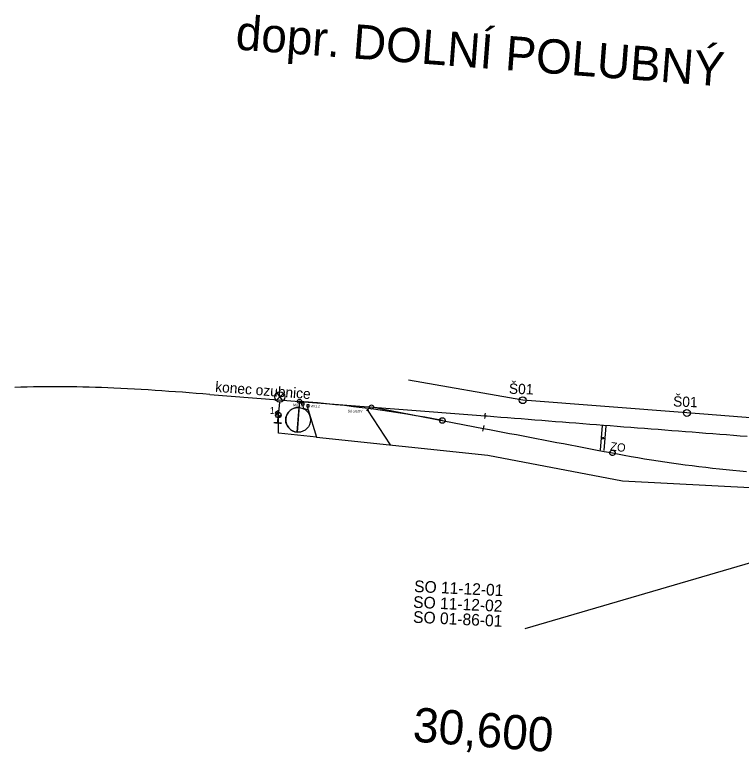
# Model space of a CAD drawing. Extents: x -669628 to -669207, y -977198 to -977075.
# Drawn here: x -669628.1 to -669522.2, y -977182.8 to -977075.4 of the extents above; entities that cross this region are included whole.
import ezdxf

# ---------------------------------------------------------------- set-up
doc = ezdxf.new("R2010")
doc.units = 0
for name, color, linetype in [('_PS_SO_číslo', 7, 'Continuous'), ('KOL_námezníky', 7, 'Continuous'), ('Navazující stavba', 7, 'Continuous'), ('SO 01-86-01', 7, 'Continuous'), ('SO 11-10-01', 7, 'Continuous'), ('SO 11-11-01', 7, 'Continuous')]:
    doc.layers.add(name, color=color, linetype=linetype)

# ---------------------------------------------------------------- blocks, each defined once
blk = doc.blocks.new('POINT_DISPLAY')
blk.add_line((0, 0), (0, 0))
blk = doc.blocks.new('Z3.50')
at = {"layer": 'KOL_námezníky'}
for p, q in [((-28, 181), (-26, -175)), ((33, -175), (32, 181))]:
    blk.add_line(p, q, dxfattribs=at)

msp = doc.modelspace()

# ---------------------------------------------------------------- linework, layer by layer
at = {"layer": '_PS_SO_číslo'}
msp.add_line((-669553.76, -977164.78), (-669513.23, -977152.92), dxfattribs=at)
at = {"layer": 'Navazující stavba'}
msp.add_line((-669599.7, -977130.69), (-669586.62, -977131.71), dxfattribs=at)
msp.add_lwpolyline([(-669599.7, -977130.69), (-669600.7, -977130.61), (-669601.69, -977130.53), (-669602.69, -977130.46), (-669603.69, -977130.38), (-669604.69, -977130.31), (-669605.68, -977130.24), (-669606.68, -977130.17), (-669607.68, -977130.1), (-669608.68, -977130.03), (-669609.68, -977129.97), (-669610.67, -977129.91), (-669611.67, -977129.86), (-669612.67, -977129.81), (-669613.67, -977129.76)], dxfattribs=at)
msp.add_arc((-669622.21, -977329.58), 200, 87.5523, 91.6942, dxfattribs=at)
at = {"layer": 'SO 01-86-01'}
for p, q in [((-669590.04, -977131.57), (-669588.95, -977130.54)), ((-669589.95, -977130.46), (-669589.04, -977131.65)), ((-669589.55, -977131.8), (-669589.67, -977133.3)), ((-669585.95, -977131.94), (-669586.33, -977131.94)), ((-669586.33, -977131.94), (-669586.33, -977132.22)), ((-669585.95, -977132.22), (-669585.95, -977131.94)), ((-669586.33, -977132.22), (-669585.95, -977132.22)), ((-669586.14, -977132.22), (-669586.1, -977132.67)), ((-669586.1, -977132.67), (-669585.38, -977132.95)), ((-669585.21, -977132.21), (-669585.58, -977132.21)), ((-669585.58, -977132.21), (-669585.58, -977132.49)), ((-669585.58, -977132.49), (-669585.21, -977132.49)), ((-669585.38, -977132.95), (-669585.39, -977132.49)), ((-669585.38, -977132.95), (-669584.14, -977136.93)), ((-669585.21, -977132.49), (-669585.21, -977132.21)), ((-669576.7, -977132.96), (-669573.41, -977138.03)), ((-669590.09, -977133.75), (-669589.59, -977133.31)), ((-669589.85, -977134.06), (-669589.31, -977133.6)), ((-669589.67, -977136.35), (-669589.71, -977133.74)), ((-669584.14, -977136.93), (-669589.67, -977136.35)), ((-669584.14, -977136.93), (-669559.19, -977139.53)), ((-669559.19, -977139.53), (-669539.54, -977143.26)), ((-669539.54, -977143.26), (-669520.01, -977144.3))]:
    msp.add_line(p, q, dxfattribs=at)
for centre, radius in [((-669589.49, -977131.06), 0.749), ((-669576.7, -977132.96), 0.0916), ((-669589.7, -977133.7), 0.4)]:
    msp.add_circle(centre, radius, dxfattribs=at)
at = {"layer": 'SO 11-10-01'}
for p, q in [((-669586.62, -977131.71), (-669586.97, -977136.19)), ((-669586.62, -977131.71), (-669559.57, -977133.81)), ((-669576.13, -977132.52), (-669559.81, -977135.63)), ((-669559.57, -977133.81), (-669559.29, -977133.83)), ((-669559.29, -977133.83), (-669558.29, -977133.91)), ((-669558.29, -977133.91), (-669557.3, -977133.99)), ((-669557.3, -977133.99), (-669556.3, -977134.07)), ((-669556.3, -977134.07), (-669555.3, -977134.14)), ((-669555.3, -977134.14), (-669554.3, -977134.22)), ((-669554.3, -977134.22), (-669553.31, -977134.3)), ((-669553.31, -977134.3), (-669552.31, -977134.38)), ((-669552.31, -977134.38), (-669551.31, -977134.46)), ((-669551.31, -977134.46), (-669550.32, -977134.53)), ((-669550.32, -977134.53), (-669549.32, -977134.61)), ((-669549.32, -977134.61), (-669548.32, -977134.69)), ((-669548.32, -977134.69), (-669547.33, -977134.77)), ((-669547.33, -977134.77), (-669546.33, -977134.84)), ((-669546.33, -977134.84), (-669545.33, -977134.92)), ((-669545.33, -977134.92), (-669544.33, -977135)), ((-669544.33, -977135), (-669543.34, -977135.08)), ((-669543.34, -977135.08), (-669542.34, -977135.15)), ((-669542.34, -977135.15), (-669541.34, -977135.23)), ((-669541.34, -977135.23), (-669540.35, -977135.31)), ((-669559.81, -977135.63), (-669558.94, -977135.8)), ((-669558.94, -977135.8), (-669557.96, -977135.99)), ((-669557.96, -977135.99), (-669556.98, -977136.17)), ((-669556.98, -977136.17), (-669556, -977136.36)), ((-669540.35, -977135.31), (-669539.35, -977135.39)), ((-669539.35, -977135.39), (-669538.35, -977135.46)), ((-669538.35, -977135.46), (-669537.36, -977135.54)), ((-669537.36, -977135.54), (-669536.36, -977135.62)), ((-669536.36, -977135.62), (-669535.36, -977135.7)), ((-669535.36, -977135.7), (-669534.36, -977135.77)), ((-669534.36, -977135.77), (-669533.37, -977135.85)), ((-669533.37, -977135.85), (-669532.37, -977135.93)), ((-669532.37, -977135.93), (-669531.37, -977136.01)), ((-669531.37, -977136.01), (-669530.38, -977136.08)), ((-669530.38, -977136.08), (-669529.38, -977136.16)), ((-669529.38, -977136.16), (-669528.38, -977136.24)), ((-669528.38, -977136.24), (-669527.39, -977136.32)), ((-669556, -977136.36), (-669555.02, -977136.55)), ((-669555.02, -977136.55), (-669554.03, -977136.74)), ((-669554.03, -977136.74), (-669553.05, -977136.92)), ((-669553.05, -977136.92), (-669552.07, -977137.11)), ((-669552.07, -977137.11), (-669551.09, -977137.3)), ((-669551.09, -977137.3), (-669550.1, -977137.48)), ((-669542.57, -977136.98), (-669542.19, -977137.11)), ((-669542.44, -977137.23), (-669542.32, -977136.85)), ((-669527.39, -977136.32), (-669526.39, -977136.4)), ((-669526.39, -977136.4), (-669525.39, -977136.47)), ((-669525.39, -977136.47), (-669524.39, -977136.55)), ((-669524.39, -977136.55), (-669523.4, -977136.63)), ((-669523.4, -977136.63), (-669522.4, -977136.71)), ((-669522.4, -977136.71), (-669521.4, -977136.78)), ((-669550.1, -977137.48), (-669549.12, -977137.67)), ((-669549.12, -977137.67), (-669548.14, -977137.86)), ((-669548.14, -977137.86), (-669547.16, -977138.05)), ((-669547.16, -977138.05), (-669546.17, -977138.23)), ((-669546.17, -977138.23), (-669545.19, -977138.42)), ((-669545.19, -977138.42), (-669544.21, -977138.61)), ((-669544.21, -977138.61), (-669543.23, -977138.8)), ((-669543.23, -977138.8), (-669542.24, -977138.98)), ((-669542.24, -977138.98), (-669541.26, -977139.17)), ((-669541.26, -977139.17), (-669541.02, -977139.22)), ((-669541.02, -977139.22), (-669540.28, -977139.36)), ((-669540.28, -977139.36), (-669539.3, -977139.54)), ((-669539.3, -977139.54), (-669538.31, -977139.71)), ((-669538.31, -977139.71), (-669537.33, -977139.88)), ((-669537.33, -977139.88), (-669536.34, -977140.05)), ((-669536.34, -977140.05), (-669535.35, -977140.21)), ((-669535.35, -977140.21), (-669534.37, -977140.36)), ((-669534.37, -977140.36), (-669533.38, -977140.51)), ((-669533.38, -977140.51), (-669532.39, -977140.66)), ((-669532.39, -977140.66), (-669531.4, -977140.8)), ((-669531.4, -977140.8), (-669530.41, -977140.93)), ((-669530.41, -977140.93), (-669529.41, -977141.06)), ((-669529.41, -977141.06), (-669528.42, -977141.18)), ((-669528.42, -977141.18), (-669527.43, -977141.3)), ((-669527.43, -977141.3), (-669526.44, -977141.41)), ((-669526.44, -977141.41), (-669525.44, -977141.52)), ((-669525.44, -977141.52), (-669524.45, -977141.62)), ((-669524.45, -977141.62), (-669523.45, -977141.72)), ((-669523.45, -977141.72), (-669522.46, -977141.81)), ((-669522.46, -977141.81), (-669521.46, -977141.9))]:
    msp.add_line(p, q, dxfattribs=at)
for points in [[(-669586.97, -977136.19), (-669586.69, -977132.6), (-669586.69, -977132.6)], [(-669541.09, -977139.61), (-669541.22, -977139.56), (-669541.33, -977139.45), (-669541.4, -977139.36), (-669541.42, -977139.22), (-669541.39, -977139.06), (-669541.32, -977138.97), (-669541.22, -977138.88), (-669541.08, -977138.82), (-669540.94, -977138.82), (-669540.81, -977138.87), (-669540.7, -977138.98), (-669540.64, -977139.07), (-669540.61, -977139.21), (-669540.64, -977139.37), (-669540.71, -977139.46), (-669540.81, -977139.55), (-669540.95, -977139.61), (-669541.09, -977139.61)]]:
    msp.add_lwpolyline(points, dxfattribs=at)
for centre, radius in [((-669586.62, -977131.71), 0.3), ((-669586.83, -977134.4), 1.8), ((-669576.13, -977132.52), 0.3), ((-669565.8, -977134.49), 0.4)]:
    msp.add_circle(centre, radius, dxfattribs=at)
for centre, radius, start, end in [((-669601.37, -977321.13), 190, 79.209, 85.549), ((-669586.83, -977134.4), 1.8, 85.5505, 265.549), ((-669576.13, -977132.52), 16.62, 354.1697, 356.9284), ((-669576.13, -977132.52), 16.62, 347.8295, 350.5882)]:
    msp.add_arc(centre, radius, start, end, dxfattribs=at)
at = {"layer": 'SO 11-11-01'}
for p, q in [((-669554.09, -977131.53), (-669570.74, -977128.59)), ((-669530.17, -977133.39), (-669554.09, -977131.53)), ((-669495.77, -977136.07), (-669530.17, -977133.39))]:
    msp.add_line(p, q, dxfattribs=at)
for centre in [(-669554.09, -977131.53), (-669530.17, -977133.39)]:
    msp.add_circle(centre, 0.5, dxfattribs=at)

# ---------------------------------------------------------------- block references
at = {"layer": 'SO 01-86-01', "rotation": -4.450857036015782}
msp.add_blockref('POINT_DISPLAY', (-669589.7, -977133.7), dxfattribs=at)
at = {"layer": 'SO 11-10-01'}
for p in [(-669586.62, -977131.71), (-669586.62, -977131.71), (-669586.62, -977131.71), (-669586.62, -977131.71), (-669565.8, -977134.49)]:
    msp.add_blockref('POINT_DISPLAY', p, dxfattribs=at)
at = {"layer": 'SO 11-10-01', "xscale": 0.01010497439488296, "yscale": 0.010104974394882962, "rotation": -5.081285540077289}
msp.add_blockref('Z3.50', (-669542.41, -977137.07), dxfattribs=at)

# ---------------------------------------------------------------- texts
at = {"layer": '_PS_SO_číslo'}
for s, p in [('SO 11-12-01', (-669569.95, -977159.47)), ('SO 11-12-02', (-669570.09, -977161.76)), ('SO 01-86-01', (-669570.1, -977163.94))]:
    msp.add_text(s, height=1.7, rotation=357.3, dxfattribs=at).set_placement(p)
at = {"layer": 'Navazující stavba'}
msp.add_text('konec ozubnice', height=1.5, rotation=355.5591, dxfattribs=at).set_placement((-669598.95, -977130.3))
at = {"layer": 'SO 01-86-01'}
msp.add_text('1', height=1, rotation=356.1, dxfattribs=at).set_placement((-669591, -977133.5))
for s, p in [('MX1.1', (-669587.54, -977132.4)), ('MX1.2', (-669585.06, -977132.56)), ('čidla EOV', (-669579.6, -977133.3))]:
    msp.add_text(s, height=0.35, dxfattribs=at).set_placement(p)
at = {"layer": 'SO 11-10-01'}
for s, height, rotation, p in [('dopr. DOLNÍ POLUBNÝ', 5, 355.6391, (-669596.04, -977080.42)), ('1', 2, 355.5519, (-669590.6, -977134.89)), ('ZO', 1.2, 352.8068, (-669541.39, -977138.81)), ('30,600', 5, 355.6391, (-669570.22, -977181.25))]:
    msp.add_text(s, height=height, rotation=rotation, dxfattribs=at).set_placement(p)
at = {"layer": 'SO 11-11-01'}
for p in [(-669556.13, -977130.58), (-669532.2, -977132.44)]:
    msp.add_text('Š01', height=1.5, rotation=357.9449, dxfattribs=at).set_placement(p)

doc.saveas('drawing.dxf')
